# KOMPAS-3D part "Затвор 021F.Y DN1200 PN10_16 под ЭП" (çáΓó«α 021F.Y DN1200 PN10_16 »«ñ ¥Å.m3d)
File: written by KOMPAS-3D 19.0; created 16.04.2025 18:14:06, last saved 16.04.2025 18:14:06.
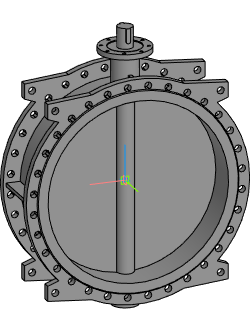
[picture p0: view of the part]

Document properties: Автор: Евгений; Полное имя файла: E:\Dendor Работа Сачек\3D для проекитирвщиков\1.6 Тип 021F.Y Затвор дисковый поворотный фланцевый\stp_Тип 021F.Y Затвор  DN40 PN10_16 под ЭП\Затвор 021F.Y DN1200 PN10_16 под ЭП.m3d

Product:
- Part/product: Затвор 021F.Y DN1200 PN10_16 под ЭП

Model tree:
1. Операция без истории:1  (labels: Затвор 021F.Y DN1200 PN10_16 под ЭП)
